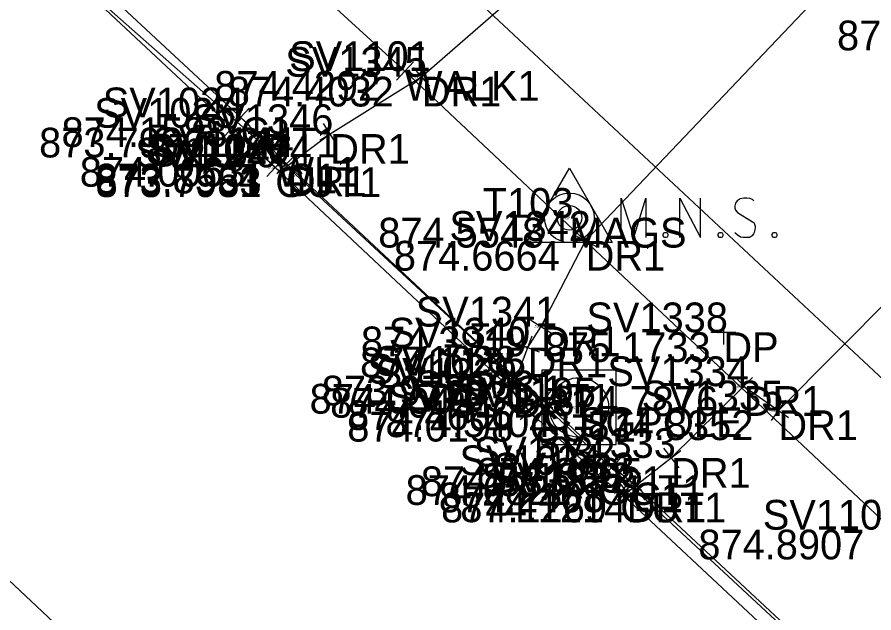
# Model space of a CAD drawing. Extents: x 1469677 to 1493262, y 375219 to 389293.
# Drawn here: x 1480162.16 to 1480196.72, y 379434.1 to 379458.14 of the extents above; entities that cross this region are included whole.
import ezdxf

# ---------------------------------------------------------------- set-up
doc = ezdxf.new("R2010")
doc.units = 0
for name, color, linetype in [('DR_X_Drive_Pipe', 7, 'Continuous'), ('DV_X_Lot_Line', 7, 'Continuous'), ('DV_X_Property_Line', 7, 'Continuous'), ('DV_X_Text', 7, 'Continuous'), ('GK_Visualization', 7, 'Continuous'), ('P-MISC', 7, 'Continuous'), ('PNTELEV', 7, 'Continuous'), ('RD_P_Text', 7, 'Continuous'), ('RW_P_Esmt_SW', 7, 'Continuous'), ('SV_X_Mon_Cells_Found', 7, 'Continuous'), ('SV_X_Text_Elevation', 7, 'Continuous'), ('Text Border', 7, 'Continuous'), ('UT_X_Misc_Cells', 7, 'Continuous')]:
    doc.layers.add(name, color=color, linetype=linetype)

msp = doc.modelspace()

# ---------------------------------------------------------------- linework, layer by layer
at = {"layer": 'DR_X_Drive_Pipe'}
msp.add_lwpolyline([(1480049.152, 379568.017), (1480068.611, 379550.193), (1480086.403, 379533.424), (1480090.024, 379530.079), (1480102.295, 379519.134), (1480111.734, 379511.473), (1480120.332, 379509.136), (1480127.535, 379501.668), (1480127.911, 379496.395), (1480140.166, 379484.084), (1480149.088, 379474.708), (1480164.726, 379459.482), (1480172.622, 379452.503), (1480197.813, 379429.111)], dxfattribs=at)
at = {"layer": 'DV_X_Lot_Line'}
msp.add_lwpolyline([(1480215.341, 379421.047), (1480197.466, 379437.463), (1480177.803, 379455.97), (1480154.79, 379476.967), (1480132.747, 379497.48), (1480113.376, 379516.728), (1480110.754, 379519.04), (1480109.877, 379518.336), (1480091.944, 379535.267), (1480093.027, 379536.619), (1480090.219, 379539.243), (1480090.463, 379539.725), (1480084.681, 379544.882), (1480083.843, 379544.144), (1480066.818, 379560.524), (1480045.662, 379580.046)], dxfattribs=at)
at = {"layer": 'DV_X_Property_Line'}
for p, q in [((1480182.707, 379449.046), (1480184.439, 379452.046)), ((1480184.439, 379452.046), (1480186.171, 379449.046)), ((1480184.439, 379450.046), (1480184.439, 379450.046)), ((1480186.171, 379449.046), (1480182.707, 379449.046))]:
    msp.add_line(p, q, dxfattribs=at)
msp.add_circle((1480184.439, 379450.046), 1, dxfattribs=at)
at = {"layer": 'P-MISC'}
msp.add_lwpolyline([(1480183.322, 379440.895), (1480186.322, 379440.895), (1480186.322, 379443.895), (1480183.322, 379443.895)], close=True, dxfattribs=at)
msp.add_circle((1480184.822, 379442.395), 1.2, dxfattribs=at)
at = {"layer": 'PNTELEV'}
for p, q in [((1480178.167, 379455.627), (1480177.439, 379456.312)), ((1480177.461, 379455.606), (1480178.146, 379456.334)), ((1480178.859, 379456.066), (1480178.105, 379455.41)), ((1480178.81, 379455.361), (1480178.154, 379456.115)), ((1480177.803, 379455.97), (1480177.803, 379455.97)), ((1480178.482, 379455.738), (1480178.482, 379455.738)), ((1480170.811, 379454.442), (1480171.544, 379453.762)), ((1480171.518, 379454.468), (1480170.837, 379453.736)), ((1480170.474, 379454.022), (1480171.205, 379453.34)), ((1480171.181, 379454.046), (1480170.498, 379453.316)), ((1480171.177, 379454.102), (1480171.177, 379454.102)), ((1480170.84, 379453.681), (1480170.84, 379453.681)), ((1480175.214, 379453.691), (1480174.366, 379453.16)), ((1480175.056, 379453.002), (1480174.525, 379453.849)), ((1480174.79, 379453.425), (1480174.79, 379453.425)), ((1480172.247, 379452.834), (1480172.997, 379452.172)), ((1480172.953, 379452.877), (1480172.291, 379452.128)), ((1480172.206, 379452.422), (1480172.942, 379451.744)), ((1480172.913, 379452.451), (1480172.235, 379451.715)), ((1480172.622, 379452.503), (1480172.622, 379452.503)), ((1480173.444, 379452.418), (1480172.643, 379451.819)), ((1480173.377, 379452.579), (1480172.665, 379451.878)), ((1480172.67, 379452.585), (1480173.372, 379451.872)), ((1480173.343, 379451.718), (1480172.744, 379452.519)), ((1480172.574, 379452.083), (1480172.574, 379452.083)), ((1480173.021, 379452.229), (1480173.021, 379452.229)), ((1480173.043, 379452.118), (1480173.043, 379452.118)), ((1480184.864, 379448.673), (1480185.326, 379449.56)), ((1480184.651, 379449.347), (1480185.539, 379448.885)), ((1480185.095, 379449.116), (1480185.095, 379449.116)), ((1480183.028, 379445.237), (1480183.565, 379446.081)), ((1480182.875, 379445.927), (1480183.718, 379445.39)), ((1480190.652, 379445.928), (1480190.652, 379444.928)), ((1480183.297, 379445.659), (1480183.297, 379445.659)), ((1480190.152, 379445.428), (1480191.152, 379445.428)), ((1480190.652, 379445.428), (1480190.652, 379445.428)), ((1480182.29, 379444.986), (1480183.226, 379444.636)), ((1480182.582, 379444.343), (1480182.933, 379445.279)), ((1480182.758, 379444.811), (1480182.758, 379444.811)), ((1480181.81, 379444.017), (1480182.541, 379443.334)), ((1480182.517, 379444.041), (1480181.834, 379443.31)), ((1480181.503, 379443.688), (1480182.231, 379443.003)), ((1480182.209, 379443.71), (1480181.524, 379442.981)), ((1480181.973, 379442.715), (1480182.323, 379443.651)), ((1480182.175, 379443.675), (1480182.175, 379443.675)), ((1480191.121, 379442.902), (1480191.832, 379443.604)), ((1480191.125, 379443.609), (1480191.828, 379442.897)), ((1480181.68, 379443.358), (1480182.616, 379443.007)), ((1480181.867, 379443.345), (1480181.867, 379443.345)), ((1480182.148, 379443.183), (1480182.148, 379443.183)), ((1480182.993, 379443.001), (1480183.765, 379442.365)), ((1480183.697, 379443.069), (1480183.061, 379442.297)), ((1480191.477, 379443.253), (1480191.477, 379443.253)), ((1480182.512, 379442.596), (1480183.165, 379441.838)), ((1480183.379, 379442.683), (1480183.379, 379442.683)), ((1480193.157, 379442.685), (1480192.583, 379441.867)), ((1480183.218, 379442.544), (1480182.46, 379441.891)), ((1480192.46, 379442.563), (1480193.279, 379441.989)), ((1480192.87, 379442.276), (1480192.87, 379442.276)), ((1480182.839, 379442.217), (1480182.839, 379442.217)), ((1480188.148, 379440.047), (1480188.937, 379440.661)), ((1480188.236, 379440.749), (1480188.85, 379439.96)), ((1480185.822, 379440.358), (1480186.546, 379439.669)), ((1480186.529, 379440.376), (1480185.84, 379439.651)), ((1480188.543, 379440.354), (1480188.543, 379440.354)), ((1480185.24, 379440), (1480185.975, 379439.322)), ((1480185.947, 379440.028), (1480185.268, 379439.294)), ((1480186.184, 379440.013), (1480186.184, 379440.013)), ((1480185.607, 379439.661), (1480185.607, 379439.661)), ((1480186.589, 379439.68), (1480187.361, 379439.045)), ((1480187.293, 379439.749), (1480186.657, 379438.977)), ((1480186.102, 379439.267), (1480186.883, 379438.643)), ((1480186.804, 379439.345), (1480186.181, 379438.564)), ((1480186.36, 379438.657), (1480187.15, 379439.271)), ((1480186.448, 379439.359), (1480187.062, 379438.57)), ((1480186.975, 379439.363), (1480186.975, 379439.363)), ((1480186.493, 379438.955), (1480186.493, 379438.955)), ((1480186.755, 379438.964), (1480186.755, 379438.964))]:
    msp.add_line(p, q, dxfattribs=at)
at = {"layer": 'RD_P_Text'}
for points in [[(1480043.308, 379574.086), (1480051.435, 379566.534), (1480067.64, 379551.083), (1480087.827, 379532.141), (1480105.189, 379515.816), (1480105.937, 379515.205), (1480115.287, 379506.588), (1480116.588, 379505.377), (1480116.999, 379505.563), (1480121.373, 379501.34), (1480121.053, 379501.135), (1480146.64, 379476.909), (1480171.177, 379454.102), (1480173.021, 379452.229), (1480182.175, 379443.675), (1480183.379, 379442.683), (1480186.184, 379440.013), (1480186.975, 379439.363), (1480207.407, 379420.301)], [(1480042.95, 379573.802), (1480051.182, 379566.018), (1480067.383, 379550.834), (1480087.586, 379531.809), (1480105.067, 379515.41), (1480105.589, 379514.887), (1480115.079, 379506.297), (1480116.303, 379505.052), (1480118.53, 379502.967), (1480120.902, 379500.821), (1480138.714, 379483.703), (1480170.84, 379453.681), (1480172.574, 379452.083), (1480181.867, 379443.345), (1480182.839, 379442.217), (1480185.607, 379439.661), (1480186.493, 379438.955), (1480206.919, 379419.855)]]:
    msp.add_lwpolyline(points, dxfattribs=at)
at = {"layer": 'SV_X_Mon_Cells_Found'}
msp.add_lwpolyline([(1477206.544, 382340.781), (1479657.335, 379947.979), (1480466.338, 379191.878)], dxfattribs=at)
at = {"layer": 'SV_X_Text_Elevation'}
msp.add_line((1479636.611, 379926.284), (1480557.828, 379065.308), dxfattribs=at)
at = {"layer": 'Text Border'}
for points in [[(1480191.959, 379467.465), (1480178.482, 379455.738), (1480174.79, 379453.425), (1480173.043, 379452.118)], [(1480182.148, 379443.183), (1480182.758, 379444.811), (1480183.297, 379445.659), (1480185.095, 379449.116), (1480197.866, 379462.558)], [(1480186.755, 379438.964), (1480188.543, 379440.354), (1480191.477, 379443.253), (1480192.87, 379442.276), (1480204.388, 379453.849)]]:
    msp.add_lwpolyline(points, dxfattribs=at)
at = {"layer": 'UT_X_Misc_Cells'}
for points in [[(1480186.529, 379449.245), (1480186.529, 379450.845), (1480187.036, 379449.245), (1480187.521, 379450.845), (1480187.521, 379449.245)], [(1480188.899, 379449.245), (1480188.899, 379450.845), (1480189.726, 379449.245), (1480189.726, 379450.845)], [(1480191.876, 379450.732), (1480191.854, 379450.757), (1480191.82, 379450.782), (1480191.721, 379450.82), (1480191.6, 379450.845), (1480191.512, 379450.845), (1480191.479, 379450.845), (1480191.335, 379450.808), (1480191.214, 379450.732), (1480191.137, 379450.631), (1480191.115, 379450.53), (1480191.115, 379450.455), (1480191.137, 379450.354), (1480191.225, 379450.266), (1480191.832, 379449.888), (1480191.887, 379449.838), (1480191.909, 379449.787), (1480191.931, 379449.712), (1480191.931, 379449.636), (1480191.92, 379449.56), (1480191.909, 379449.51), (1480191.887, 379449.447), (1480191.865, 379449.397), (1480191.842, 379449.359), (1480191.809, 379449.321), (1480191.776, 379449.296), (1480191.732, 379449.271), (1480191.699, 379449.258), (1480191.6, 379449.245), (1480191.446, 379449.245), (1480191.347, 379449.271), (1480191.203, 379449.359), (1480191.115, 379449.434)], [(1480188.293, 379449.46), (1480188.348, 379449.46), (1480188.381, 379449.434), (1480188.414, 379449.384), (1480188.414, 379449.321), (1480188.381, 379449.271), (1480188.348, 379449.245), (1480188.293, 379449.245), (1480188.26, 379449.271), (1480188.227, 379449.321), (1480188.227, 379449.384), (1480188.26, 379449.434), (1480188.293, 379449.46)], [(1480190.509, 379449.46), (1480190.564, 379449.46), (1480190.597, 379449.434), (1480190.63, 379449.384), (1480190.63, 379449.321), (1480190.597, 379449.271), (1480190.564, 379449.245), (1480190.509, 379449.245), (1480190.476, 379449.271), (1480190.443, 379449.321), (1480190.443, 379449.384), (1480190.476, 379449.434), (1480190.509, 379449.46)], [(1480192.691, 379449.46), (1480192.746, 379449.46), (1480192.78, 379449.434), (1480192.812, 379449.384), (1480192.812, 379449.321), (1480192.78, 379449.271), (1480192.746, 379449.245), (1480192.691, 379449.245), (1480192.658, 379449.271), (1480192.625, 379449.321), (1480192.625, 379449.384), (1480192.658, 379449.434), (1480192.691, 379449.46)]]:
    msp.add_lwpolyline(points, dxfattribs=at)
msp.add_circle((1480184.44, 379450.045), 0.497, dxfattribs=at)

# ---------------------------------------------------------------- texts
at = {"layer": 'DV_X_Text'}
for s, height, p in [('875.3321', 1.2, (1480195.236, 379456.805)), ('874.4292', 1.2, (1480170.113, 379454.77)), ('874.4032', 1.2, (1480170.659, 379454.538)), ('874.43', 0.06, (1480177.522, 379455.91)), ('874.40', 0.06, (1480178.196, 379455.678)), ('874.1588', 1.2, (1480163.95, 379452.902)), ('874.16', 0.06, (1480170.916, 379454.042)), ('873.7936', 1.2, (1480163.045, 379452.481)), ('873.79', 0.06, (1480170.559, 379453.621)), ('874.1004', 1.2, (1480167.355, 379452.225)), ('874.10', 0.06, (1480174.528, 379453.365)), ('874.0063', 1.2, (1480164.686, 379451.303)), ('873.8564', 1.2, (1480165.311, 379451.029)), ('874.01', 0.06, (1480172.358, 379452.443)), ('873.7933', 1.2, (1480165.324, 379450.918)), ('873.7981', 1.2, (1480165.325, 379450.883)), ('873.80', 0.06, (1480172.288, 379452.023)), ('873.86', 0.06, (1480172.736, 379452.169)), ('873.79', 0.06, (1480172.762, 379452.058)), ('874.5548', 1.2, (1480176.729, 379448.846)), ('874.55', 0.06, (1480184.158, 379449.986)), ('874.6664', 1.2, (1480177.357, 379447.916)), ('874.67', 0.06, (1480184.813, 379449.056)), ('874.3919', 1.2, (1480176.031, 379444.459)), ('874.39', 0.06, (1480183.015, 379445.599)), ('875.1733', 1.2, (1480183.443, 379444.228)), ('875.17', 0.06, (1480190.396, 379445.368)), ('874.1135', 1.2, (1480175.994, 379443.611)), ('874.11', 0.06, (1480182.524, 379444.751)), ('873.9738', 1.2, (1480174.447, 379442.475)), ('873.97', 0.06, (1480181.893, 379443.615)), ('874.0502', 1.2, (1480173.959, 379442.145)), ('874.05', 0.06, (1480181.581, 379443.285)), ('874.7876', 1.2, (1480183.748, 379442.053)), ('874.0451', 1.2, (1480174.786, 379441.983)), ('874.05', 0.06, (1480181.862, 379443.123)), ('874.79', 0.06, (1480191.197, 379443.193)), ('874.4606', 1.2, (1480175.471, 379441.483)), ('874.46', 0.06, (1480183.094, 379442.623)), ('874.0198', 1.2, (1480175.479, 379441.017)), ('874.5404', 1.2, (1480177.018, 379441.195)), ('874.54', 0.06, (1480184.542, 379442.335)), ('874.8352', 1.2, (1480185.169, 379441.076)), ('874.84', 0.06, (1480192.59, 379442.216)), ('874.02', 0.06, (1480182.553, 379442.157)), ('874.3305', 1.2, (1480180.701, 379439.154)), ('874.33', 0.06, (1480188.261, 379440.294)), ('874.5338', 1.2, (1480178.446, 379438.813)), ('874.53', 0.06, (1480185.903, 379439.953)), ('874.0822', 1.2, (1480177.832, 379438.461)), ('874.08', 0.06, (1480185.32, 379439.601)), ('874.2408', 1.2, (1480179.171, 379438.163)), ('874.24', 0.06, (1480186.696, 379439.303)), ('874.1269', 1.2, (1480179.265, 379437.755)), ('874.1214', 1.2, (1480180.039, 379437.764)), ('874.13', 0.06, (1480186.236, 379438.895)), ('874.12', 0.06, (1480186.499, 379438.904)), ('874.8907', 1.2, (1480189.643, 379436.263))]:
    msp.add_text(s, height=height, dxfattribs=at).set_placement(p)
at = {"layer": 'GK_Visualization'}
for s, p in [('WALK1', (1480177.803, 379454.77)), ('DR1', (1480178.482, 379454.538)), ('C1', (1480171.177, 379452.902)), ('GUT1', (1480170.84, 379452.481)), ('DR1', (1480174.79, 379452.225)), ('WL1', (1480172.622, 379451.303)), ('C1', (1480173.021, 379451.029)), ('GUT1', (1480172.574, 379450.883)), ('DR1', (1480173.043, 379450.918)), ('MAGS', (1480184.439, 379448.846)), ('DR1', (1480185.095, 379447.916)), ('DR1', (1480183.297, 379444.459)), ('DP', (1480190.652, 379444.228)), ('DR1', (1480182.758, 379443.611)), ('C1', (1480182.175, 379442.475)), ('GUT1', (1480181.867, 379442.145)), ('DR1', (1480182.148, 379441.983)), ('DR1', (1480191.477, 379442.053)), ('C1', (1480183.379, 379441.483)), ('GUT1', (1480182.839, 379441.017)), ('SGPOLE', (1480184.822, 379441.195)), ('DR1', (1480192.87, 379441.076)), ('DR1', (1480188.543, 379439.154)), ('C1', (1480186.184, 379438.813)), ('GUT1', (1480185.607, 379438.461)), ('C1', (1480186.975, 379438.163)), ('GUT1', (1480186.493, 379437.755)), ('DR1', (1480186.755, 379437.764))]:
    msp.add_text(s, height=1.2, dxfattribs=at).set_placement(p)
at = {"layer": 'RW_P_Esmt_SW'}
for s, height, p in [('SV1101', 1.2, (1480173.135, 379455.97)), ('SV1345', 1.2, (1480172.975, 379455.738)), ('SV1101', 0.06, (1480177.57, 379455.97)), ('SV1345', 0.06, (1480178.207, 379455.738)), ('SV1024', 1.2, (1480165.613, 379454.102)), ('SV1025', 1.2, (1480165.266, 379453.681)), ('SV1346', 1.2, (1480169.207, 379453.425)), ('SV1024', 0.06, (1480170.899, 379454.102)), ('SV1144', 1.2, (1480167.616, 379452.503)), ('SV1025', 0.06, (1480170.561, 379453.681)), ('SV1026', 1.2, (1480166.925, 379452.083)), ('SV1027', 1.2, (1480167.447, 379452.229)), ('SV1347', 1.2, (1480167.536, 379452.118)), ('SV1346', 0.06, (1480174.511, 379453.425)), ('SV1144', 0.06, (1480172.372, 379452.503)), ('SV1027', 0.06, (1480172.742, 379452.229)), ('SV1026', 0.06, (1480172.292, 379452.083)), ('SV1347', 0.06, (1480172.768, 379452.118)), ('T103', 1.2, (1480180.944, 379450.046)), ('SV1342', 1.2, (1480179.597, 379449.116)), ('T103', 0.06, (1480184.264, 379450.046)), ('SV1342', 0.06, (1480184.82, 379449.116)), ('SV1341', 1.2, (1480178.24, 379445.659)), ('SV1338', 1.2, (1480185.125, 379445.428)), ('SV1340', 1.2, (1480177.146, 379444.811)), ('SV1341', 0.06, (1480183.044, 379445.659)), ('SV1338', 0.06, (1480190.376, 379445.428)), ('SV1028', 1.2, (1480176.592, 379443.675)), ('SV1340', 0.06, (1480182.477, 379444.811)), ('SV1029', 1.2, (1480176.284, 379443.345)), ('SV1339', 1.2, (1480176.621, 379443.183)), ('SV1334', 1.2, (1480185.969, 379443.253)), ('SV1031', 1.2, (1480178.218, 379442.683)), ('SV1195', 1.2, (1480179.797, 379442.395)), ('SV1028', 0.06, (1480181.896, 379443.675)), ('SV1030', 1.2, (1480177.123, 379442.217)), ('SV1029', 0.06, (1480181.588, 379443.345)), ('SV1335', 1.2, (1480187.353, 379442.276)), ('SV1334', 0.06, (1480191.202, 379443.253)), ('SV1339', 0.06, (1480181.872, 379443.183)), ('SV1031', 0.06, (1480183.121, 379442.683)), ('SV1030', 0.06, (1480182.553, 379442.217)), ('SV1195', 0.06, (1480184.571, 379442.395)), ('SV1335', 0.06, (1480192.594, 379442.276)), ('SV1333', 1.2, (1480183.026, 379440.354)), ('SV1032', 1.2, (1480180.582, 379440.013)), ('SV1034', 1.2, (1480180.005, 379439.661)), ('SV1033', 1.2, (1480181.364, 379439.363)), ('SV1035', 1.2, (1480180.881, 379438.955)), ('SV1332', 1.2, (1480181.247, 379438.964)), ('SV1333', 0.06, (1480188.267, 379440.354)), ('SV1032', 0.06, (1480185.904, 379440.013)), ('SV1034', 0.06, (1480185.327, 379439.661)), ('SV1033', 0.06, (1480186.694, 379439.363)), ('SV1035', 0.06, (1480186.212, 379438.955)), ('SV1332', 0.06, (1480186.48, 379438.964)), ('SV1100', 1.2, (1480192.242, 379437.463))]:
    msp.add_text(s, height=height, dxfattribs=at).set_placement(p)

doc.saveas('drawing.dxf')
